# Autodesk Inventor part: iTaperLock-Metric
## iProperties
Author: scotta
Shininess: 64.0
Angle Display Precision: 2
Document Length Units: 11269
Document Angle Units: 11283
Document Time Units: 11279
Document Mass Units: 11290
Document Length Units Precision: 3
Document Angle Units Precision: 2
Compacted: True
PropertySet Name: _Private Model Information
Created: 2002-04
Part Number: iTaperLock-Metric
Material: Steel, Mild
Document SubType Name: Modeling
Designer: scotta
Control State: 0
Master: False
Checked Out: False
PropertySet Name: Design Tracking Control
Density: 0.0
Volumn: 0.0
Area: 0.0
PropertySet Name: Model Information
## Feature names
1. Base Extrusion [Extrusion]
2. Features [Extrusion]
3. Extraction Thread [Hole]
4. Installation Holes [Hole]
